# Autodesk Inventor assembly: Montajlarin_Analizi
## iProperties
Created: 2004-11
Part Number: Montajlarin_Analizi
Cost Center: 0 lbmass
Document SubType Name: Assembly
Designer: busseym
Manufacturer: Standard
Standards Organization: Custom
Description: SWING ARM, LCD FLAT PANEL
Stock Number: SA-LCD-17
Dept. ID: Product Design
Description #2: ---
Finish #1: ---
Finish #2: ---
Material ID: ---
Project Number: ---
Author: busseym
